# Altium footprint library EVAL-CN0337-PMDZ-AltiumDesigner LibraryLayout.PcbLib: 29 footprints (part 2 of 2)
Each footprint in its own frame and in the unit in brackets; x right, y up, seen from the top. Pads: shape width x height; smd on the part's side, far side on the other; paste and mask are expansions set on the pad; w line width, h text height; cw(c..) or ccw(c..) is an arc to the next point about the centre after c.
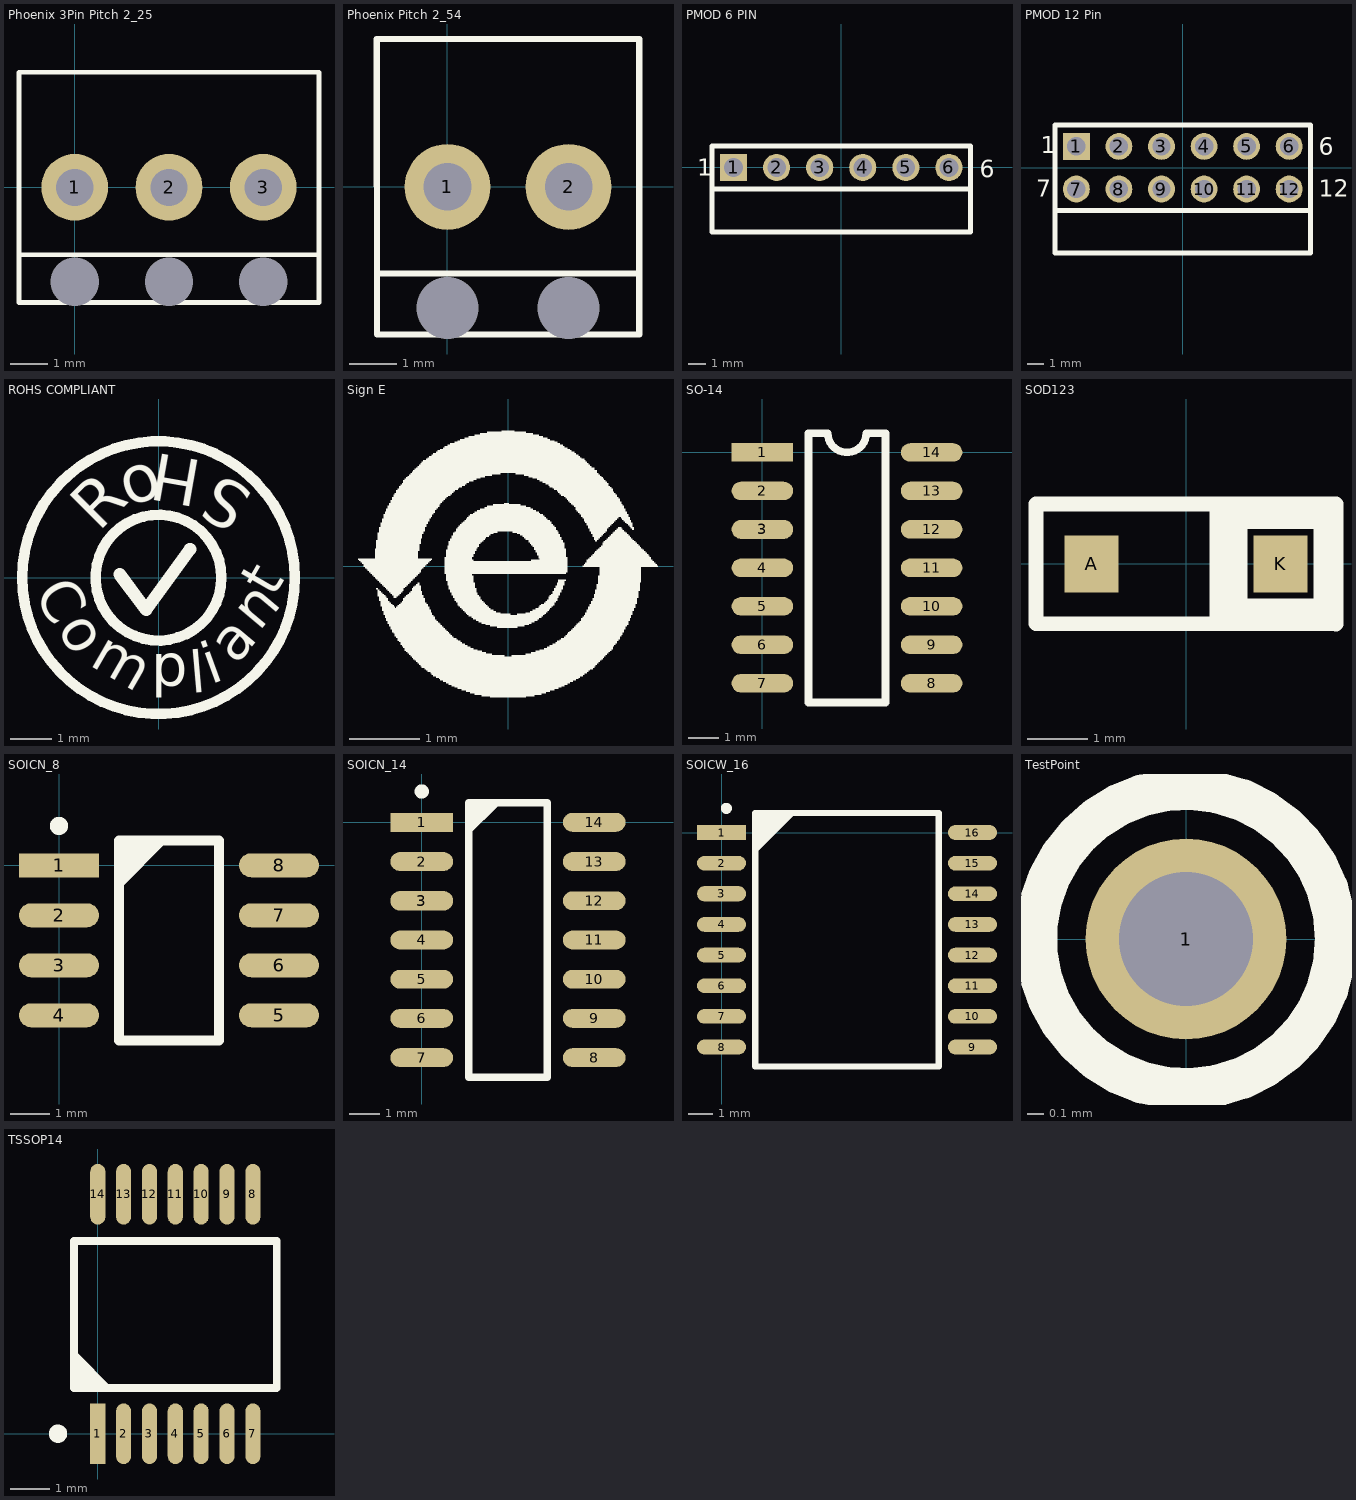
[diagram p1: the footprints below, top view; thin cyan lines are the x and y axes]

## Phoenix 3Pin Pitch 2_25 [mm]
pads (6):
  round 1.8 hole 1: 1(0,0) 2(2.54,0) 3(5.08,0)
  round 0 hole 1.3: ""(0,-2.54) ""(2.54,-2.54) ""(5.08,-2.54)
Top Overlay:
  lines w0.127: -1.5,-3.1 -1.5,3.1 ; -1.483,3.1 6.58,3.1 6.58,-3.1 ; -1.48,-3.1 6.579,-3.1 ; -1.455,-1.817 6.58,-1.817

## Phoenix Pitch 2_54 [mm]
pads (4):
  round 1.8 hole 1: 1(0,0) 2(2.54,0)
  round 0 hole 1.3: ""(0,-2.54) ""(2.54,-2.54)
Top Overlay:
  lines w0.127: -1.455,-1.817 4.02,-1.817 ; -1.483,3.1 -1.48,-3.1 4.02,-3.1 4.02,3.1 -1.483,3.1

## PMOD 6 PIN [mm]
pads (6):
  rect 1.6x1.6 hole 1.1: 1(-6.35,0)
  round 1.6 hole 1.1: 2(-3.81,0) 3(-1.27,0) 4(1.27,0) 5(3.81,0) 6(6.35,0)
Top Overlay:
  lines w0.305: -7.62,-1.272 7.62,-1.27 ; 7.62,-1.27 7.62,-3.81 -7.62,-3.81 -7.62,-1.27 -7.62,1.27 7.62,1.27 7.62,-1.27
  text "1" at -8.504,-0.476 h1.02
  text "6" at 8.167,-0.578 h1.02

## PMOD 12 Pin [mm]
pads (12):
  rect 1.6x1.6 hole 1.1: 1(-6.35,1.27)
  round 1.6 hole 1.1: 2(-3.81,1.27) 3(-1.27,1.27) 4(1.27,1.27) 5(3.81,1.27) 6(6.35,1.27) 7(-6.35,-1.27) 8(-3.81,-1.27) 9(-1.27,-1.27) 10(1.27,-1.27) 11(3.81,-1.27) 12(6.35,-1.27)
Top Overlay:
  lines w0.305: -7.62,-2.542 7.62,-2.54 ; 7.62,-2.54 7.62,1.27 7.62,2.54 6.35,2.54 -6.35,2.54 -7.62,2.54 -7.62,1.27 -7.62,-2.54 -7.62,-5.08 7.62,-5.08 7.62,-2.54
  text "12" at 8.105,-1.739 h1.02
  text "6" at 8.131,0.78 h1.02
  text "7" at -8.761,-1.727 h1.02
  text "1" at -8.491,0.854 h1.02

## ROHS COMPLIANT [mil]
Top Overlay:
  circle w10: c0,0 r60
  circle w10: c0,0 r130
  lines w12: -36.91,3.04 -11.87,-30.68 30,27
  text "S" at 92,80 h45
  text "H" at 43,111 h45
  text "o" at -29,67 h45
  text "R" at -57,43 h45
  text "C" at -119,-15 h40
  text "o" at -97,-48 h40
  text "m" at -67,-83 h40
  text "p" at -7,-103 h40
  text "l" at 31,-110 h40
  text "i" at 50,-102 h40
  text "a" at 74,-84 h40
  text "n" at 96,-52 h40
  text "t" at 110,-20 h40

## Sign E [mil]
Top Overlay:
  drawing of 495 lines, arcs and shapes, not listed

## SO-14 [mil]
height 68.9
pads (14):
  rect 80x24 smd: 1(0,0)
  oval 80x24 smd: 2(0,-50) 4(0,-150) 5(0,-200) 6(0,-250) 7(0,-300) 8(220,-300) 9(220,-250) 10(220,-200) 11(220,-150) 12(220,-100) 13(220,-50) 14(220,0)
  oval 80x25 smd: 3(0,-100)
Top Overlay:
  lines w10: 60,-325 160,-325 160,25 135,25 cw(c110,25) 85,25 60,25 60,-325

## SOD123 [mm]
pads (2):
  rect 0.9x0.95 smd: A(-1.575,0) K(1.575,0)
Top Overlay:
  rectangle: 0.388,-0.999 1.023,1
  rectangle: 0.931,0.579 2.5,1
  rectangle: 2.128,-1.002 2.5,0.653
  rectangle: 1.014,-1.001 2.155,-0.577
  lines w0.254: -2.5,-0.995 2.5,-1.002 ; -2.5,1 2.5,1 2.5,-1.002 ; -2.499,-0.995 -2.499,0.997

## SOICN_8 [mil]
pads (8):
  rect 80x24 smd: 1(0,0)
  oval 80x24 smd: 2(0,-50) 3(0,-100) 4(0,-150) 5(220,-150) 6(220,-100) 7(220,-50) 8(220,0)
Top Overlay:
  circle w11.81: c0,39.37 r3.15
  region: 65.01,-19.31 104.4,20.09 65.01,20.09
  lines w10: 60,-175 160,-175 160,25 135,25 60,25 60,-175

## SOICN_14 [mil]
pads (14):
  rect 80x24 smd: 1(0,0)
  oval 80x24 smd: 2(0,-50) 4(0,-150) 5(0,-200) 6(0,-250) 7(0,-300) 8(220,-300) 9(220,-250) 10(220,-200) 11(220,-150) 12(220,-100) 13(220,-50) 14(220,0)
  oval 80x25 smd: 3(0,-100)
Top Overlay:
  circle w11.81: c0,39.37 r3.15
  region: 59.3,-16.7 98.7,22.7 59.3,22.7
  lines w10: 79,25 160,25 160,-325 60,-325 60,25 85,25

## SOICW_16 [mil]
pads (16):
  rect 80x24 smd: 1(0,0)
  oval 80x24 smd: 2(0,-50) 4(0,-150) 5(0,-200) 6(0,-250) 7(0,-300) 8(0,-350) 9(409.45,-350) 10(409.45,-300) 11(409.45,-250) 12(409.45,-200) 13(409.45,-150) 14(409.45,-100) 15(409.45,-50) 16(409.45,0)
  oval 80x25 smd: 3(0,-100)
Top Overlay:
  circle w11.81: c7.87,39.37 r3.15
  region: 55.12,-34.55 121.01,31.69 55.12,31.69
  lines w10: 55.12,-381.69 354.33,-381.69 354.33,31.69 55.12,31.69 55.12,-381.69

## TestPoint [mil]
pads (1):
  round 48 hole 32: 1(0,0)
Top Overlay:
  circle w10: c0,0 r35.85

## TSSOP14 [mil]
pads (14):
  rect 15x60 smd: 1(0,0)
  oval 15x60 smd: 2(25.59,0) 3(51.18,0) 4(76.77,0) 5(102.36,0) 6(127.95,0) 7(153.54,0) 8(153.54,237.01) 9(127.95,237.01) 10(102.36,237.01) 11(76.77,237.01) 12(51.18,237.01) 13(25.59,237.01) 14(0,237.01)
Top Overlay:
  circle w11.81: c-39.37,0 r3.15
  region: 14.97,44.59 -21.96,81.58 -22,81.58 -22,50 -6.17,44.59
  lines w7.87: -23.62,45.28 177,45.28 ; -23.62,46.19 -23.62,190.91 177.17,190.91 177.17,46.02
